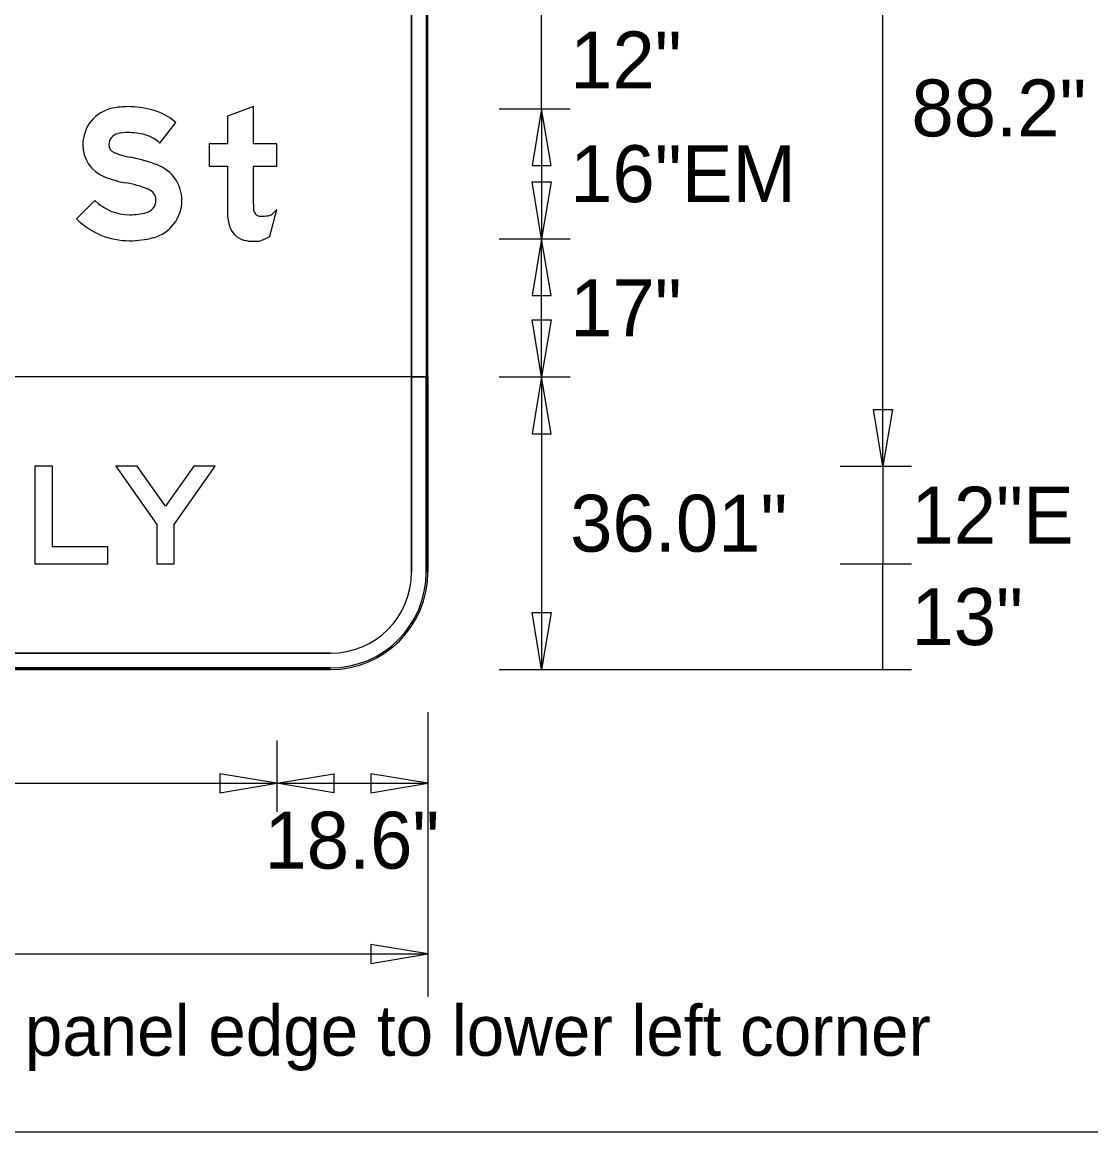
# Model space of a CAD drawing. Extents: x 2149934 to 2150188, y 145114 to 145238.
# Drawn here: x 2150101.62 to 2150112.58, y 145143.48 to 145154.85 of the extents above; entities that cross this region are included whole.
import ezdxf

# ---------------------------------------------------------------- set-up
doc = ezdxf.new("R2010")
doc.units = 0
for name, color, linetype in [('GSBWFILL', 7, 'Continuous'), ('GSCOLORFILL', 7, 'Continuous'), ('GSDIMS', 7, 'Continuous'), ('GSOUTLINE', 7, 'Continuous'), ('Level 1', 7, 'Continuous')]:
    doc.layers.add(name, color=color, linetype=linetype)

msp = doc.modelspace()

# ---------------------------------------------------------------- linework, layer by layer
at = {"layer": 'GSBWFILL'}
for p, q in [((2150105.612, 145163.216), (2150105.612, 145149.216)), ((2150105.779, 145149.216), (2150105.779, 145163.216)), ((2150104.159, 145152.659), (2150104.229, 145152.935)), ((2150105.779, 145151.217), (2150090.279, 145151.217)), ((2150105.612, 145151.05), (2150105.612, 145151.217)), ((2150105.612, 145151.217), (2150105.779, 145151.217)), ((2150105.779, 145151.217), (2150105.779, 145149.216)), ((2150105.779, 145149.216), (2150105.779, 145151.217)), ((2150105.612, 145149.216), (2150105.612, 145151.05)), ((2150091.279, 145148.383), (2150104.779, 145148.383)), ((2150104.779, 145148.383), (2150091.28, 145148.383)), ((2150104.779, 145148.216), (2150091.279, 145148.216)), ((2150091.279, 145148.216), (2150104.779, 145148.216)), ((2150091.28, 145148.216), (2150104.779, 145148.216))]:
    msp.add_line(p, q, dxfattribs=at)
for points in [[(2150103.989, 145152.987), (2150103.989, 145153.377), (2150104.229, 145153.377), (2150104.229, 145153.607), (2150103.989, 145153.607), (2150103.989, 145153.99), (2150103.723, 145153.889), (2150103.723, 145153.607), (2150103.536, 145153.607), (2150103.536, 145153.377), (2150103.723, 145153.377), (2150103.723, 145152.907)], [(2150103.03, 145153.615), (2150103.194, 145153.826)], [(2150102.364, 145153.026), (2150102.176, 145152.836)]]:
    msp.add_lwpolyline(points, dxfattribs=at)
for points in [[(2150102.498, 145149.3), (2150102.498, 145149.475), (2150101.928, 145149.475), (2150101.928, 145150.3), (2150101.748, 145150.3), (2150101.748, 145149.3)], [(2150103.178, 145149.705), (2150103.598, 145150.3), (2150103.378, 145150.3), (2150103.088, 145149.89), (2150102.799, 145150.3), (2150102.578, 145150.3), (2150102.998, 145149.705), (2150102.998, 145149.3), (2150103.178, 145149.3)]]:
    msp.add_lwpolyline(points, close=True, dxfattribs=at)
for radius in [1, 0.833, 1, 0.833, 1]:
    msp.add_arc((2150104.779, 145149.216), radius, 270, 0, dxfattribs=at)
for centre, major_axis, ratio, start_param, end_param in [((2150102.703, 145153.203), (0, 0.785), 0.999996, 0, 0.202758), ((2150102.703, 145153.025), (0, 0.963), 0.999996, 6.026234, 6.283185), ((2150102.622, 145153.598), (0, 0.382), 0.999996, 0.202758, 1.570796), ((2150102.792, 145153.365), (0, 0.611), 0.999996, 5.565152, 6.026234), ((2150102.622, 145153.598), (0, 0.115), 0.999996, 0.202758, 1.570796), ((2150102.703, 145153.203), (0, 0.519), 0.999996, 0, 0.202758), ((2150102.703, 145153.025), (0, 0.697), 0.999996, 6.026234, 6.283185), ((2150102.792, 145153.365), (0, 0.345), 0.999996, 5.523837, 6.026234), ((2150102.593, 145153.598), (0, 0.354), 0.999996, 1.570796, 2.761249), ((2150102.593, 145153.598), (0, 0.0872), 0.999996, 1.570796, 2.761249), ((2150102.884, 145154.325), (0, 0.87), 0.999996, 2.761249, 2.95744), ((2150102.427, 145151.874), (0, 1.623), 0.999996, 5.918637, 6.099033), ((2150102.868, 145153.027), (0, 0.388), 0.999996, 4.712389, 5.918637), ((2150102.884, 145154.325), (0, 1.137), 0.999996, 2.761249, 2.95744), ((2150102.427, 145151.874), (0, 1.357), 0.999996, 5.918637, 6.099033), ((2150102.868, 145153.027), (0, 0.122), 0.999996, 4.712389, 5.918637), ((2150102.719, 145153.384), (0, 0.504), 0.999996, 2.360607, 3.141593), ((2150102.86, 145153.027), (0, 0.129), 0.999996, 3.401517, 4.712389), ((2150102.86, 145153.027), (0, 0.396), 0.999996, 3.401517, 4.712389), ((2150105.659, 145152.987), (0, 1.669), 0.999994, 1.570796, 1.606005), ((2150102.719, 145153.558), (0, 0.678), 0.999996, 3.141593, 3.401517), ((2150104.24, 145152.907), (0, 0.517), 0.999994, 1.570796, 1.830698), ((2150104.066, 145152.941), (0, 0.0767), 0.999994, 1.74085, 2.407828), ((2150104.068, 145152.944), (0, 0.0803), 0.999994, 2.407828, 3.141593), ((2150104.068, 145153.285), (0, 0.421), 0.999994, 3.141593, 3.310762), ((2150104.123, 145152.968), (0, 0.1), 0.999994, 3.310762, 3.756278), ((2150104.054, 145153.066), (0, 0.219), 0.999994, 3.756278, 4.071638), ((2150102.719, 145153.384), (0, 0.771), 0.999996, 2.360607, 3.141593), ((2150103.95, 145152.829), (0, 0.217), 0.999994, 1.830698, 2.869526), ((2150102.719, 145153.558), (0, 0.945), 0.999996, 3.141593, 3.401517), ((2150103.989, 145152.972), (0, 0.365), 0.999994, 2.869526, 3.141593), ((2150103.981, 145152.921), (0, 0.317), 0.999994, 3.427755, 3.738844), ((2150103.989, 145153.133), (0, 0.526), 0.999994, 3.141593, 3.205734), ((2150104.009, 145152.824), (0, 0.217), 0.999994, 3.205734, 3.427755)]:
    msp.add_ellipse(centre, major_axis=major_axis, ratio=ratio, start_param=start_param, end_param=end_param, dxfattribs=at)
at = {"layer": 'GSCOLORFILL'}
for p, q in [((2150105.612, 145163.216), (2150105.612, 145149.216)), ((2150105.762, 145163.216), (2150105.762, 145149.216)), ((2150105.779, 145149.216), (2150105.779, 145163.216)), ((2150105.779, 145149.216), (2150105.779, 145163.216)), ((2150105.779, 145149.216), (2150105.779, 145163.216)), ((2150104.159, 145152.659), (2150104.229, 145152.935)), ((2150105.779, 145151.217), (2150090.279, 145151.217)), ((2150105.612, 145151.05), (2150105.612, 145151.217)), ((2150105.612, 145151.217), (2150105.779, 145151.217)), ((2150105.762, 145151.2), (2150105.762, 145151.217)), ((2150105.762, 145151.217), (2150105.779, 145151.217)), ((2150105.762, 145149.216), (2150105.762, 145151.2)), ((2150105.779, 145149.216), (2150105.779, 145151.217)), ((2150105.779, 145151.217), (2150105.779, 145149.216)), ((2150105.779, 145151.217), (2150105.779, 145149.216)), ((2150105.612, 145149.216), (2150105.612, 145151.05)), ((2150091.279, 145148.383), (2150104.779, 145148.383)), ((2150104.779, 145148.383), (2150091.28, 145148.383)), ((2150104.779, 145148.233), (2150091.279, 145148.233)), ((2150091.279, 145148.233), (2150104.779, 145148.233)), ((2150091.279, 145148.216), (2150104.779, 145148.216)), ((2150091.279, 145148.216), (2150104.779, 145148.216)), ((2150091.279, 145148.216), (2150104.779, 145148.216)), ((2150104.779, 145148.216), (2150091.279, 145148.216)), ((2150104.779, 145148.216), (2150091.279, 145148.216)), ((2150091.28, 145148.216), (2150104.779, 145148.216))]:
    msp.add_line(p, q, dxfattribs=at)
for points in [[(2150103.989, 145152.987), (2150103.989, 145153.377), (2150104.229, 145153.377), (2150104.229, 145153.607), (2150103.989, 145153.607), (2150103.989, 145153.99), (2150103.723, 145153.889), (2150103.723, 145153.607), (2150103.536, 145153.607), (2150103.536, 145153.377), (2150103.723, 145153.377), (2150103.723, 145152.907)], [(2150103.03, 145153.615), (2150103.194, 145153.826)], [(2150102.364, 145153.026), (2150102.176, 145152.836)]]:
    msp.add_lwpolyline(points, dxfattribs=at)
for points in [[(2150102.498, 145149.3), (2150102.498, 145149.475), (2150101.928, 145149.475), (2150101.928, 145150.3), (2150101.748, 145150.3), (2150101.748, 145149.3)], [(2150103.178, 145149.705), (2150103.598, 145150.3), (2150103.378, 145150.3), (2150103.088, 145149.89), (2150102.799, 145150.3), (2150102.578, 145150.3), (2150102.998, 145149.705), (2150102.998, 145149.3), (2150103.178, 145149.3)]]:
    msp.add_lwpolyline(points, close=True, dxfattribs=at)
for radius in [1, 1, 0.833, 1, 0.983, 1, 1, 0.833, 1, 0.983]:
    msp.add_arc((2150104.779, 145149.216), radius, 270, 0, dxfattribs=at)
for centre, major_axis, ratio, start_param, end_param in [((2150102.703, 145153.203), (0, 0.785), 0.999996, 0, 0.202758), ((2150102.703, 145153.025), (0, 0.963), 0.999996, 6.026234, 6.283185), ((2150102.622, 145153.598), (0, 0.382), 0.999996, 0.202758, 1.570796), ((2150102.792, 145153.365), (0, 0.611), 0.999996, 5.565152, 6.026234), ((2150102.622, 145153.598), (0, 0.115), 0.999996, 0.202758, 1.570796), ((2150102.703, 145153.203), (0, 0.519), 0.999996, 0, 0.202758), ((2150102.703, 145153.025), (0, 0.697), 0.999996, 6.026234, 6.283185), ((2150102.792, 145153.365), (0, 0.345), 0.999996, 5.523837, 6.026234), ((2150102.593, 145153.598), (0, 0.354), 0.999996, 1.570796, 2.761249), ((2150102.593, 145153.598), (0, 0.0872), 0.999996, 1.570796, 2.761249), ((2150102.884, 145154.325), (0, 0.87), 0.999996, 2.761249, 2.95744), ((2150102.427, 145151.874), (0, 1.623), 0.999996, 5.918637, 6.099033), ((2150102.868, 145153.027), (0, 0.388), 0.999996, 4.712389, 5.918637), ((2150102.884, 145154.325), (0, 1.137), 0.999996, 2.761249, 2.95744), ((2150102.427, 145151.874), (0, 1.357), 0.999996, 5.918637, 6.099033), ((2150102.868, 145153.027), (0, 0.122), 0.999996, 4.712389, 5.918637), ((2150102.719, 145153.384), (0, 0.504), 0.999996, 2.360607, 3.141593), ((2150102.86, 145153.027), (0, 0.129), 0.999996, 3.401517, 4.712389), ((2150102.86, 145153.027), (0, 0.396), 0.999996, 3.401517, 4.712389), ((2150105.659, 145152.987), (0, 1.669), 0.999994, 1.570796, 1.606005), ((2150102.719, 145153.558), (0, 0.678), 0.999996, 3.141593, 3.401517), ((2150104.24, 145152.907), (0, 0.517), 0.999994, 1.570796, 1.830698), ((2150104.066, 145152.941), (0, 0.0767), 0.999994, 1.74085, 2.407828), ((2150104.068, 145152.944), (0, 0.0803), 0.999994, 2.407828, 3.141593), ((2150104.068, 145153.285), (0, 0.421), 0.999994, 3.141593, 3.310762), ((2150104.123, 145152.968), (0, 0.1), 0.999994, 3.310762, 3.756278), ((2150104.054, 145153.066), (0, 0.219), 0.999994, 3.756278, 4.071638), ((2150102.719, 145153.384), (0, 0.771), 0.999996, 2.360607, 3.141593), ((2150103.95, 145152.829), (0, 0.217), 0.999994, 1.830698, 2.869526), ((2150102.719, 145153.558), (0, 0.945), 0.999996, 3.141593, 3.401517), ((2150103.989, 145152.972), (0, 0.365), 0.999994, 2.869526, 3.141593), ((2150103.981, 145152.921), (0, 0.317), 0.999994, 3.427755, 3.738844), ((2150103.989, 145153.133), (0, 0.526), 0.999994, 3.141593, 3.205734), ((2150104.009, 145152.824), (0, 0.217), 0.999994, 3.205734, 3.427755)]:
    msp.add_ellipse(centre, major_axis=major_axis, ratio=ratio, start_param=start_param, end_param=end_param, dxfattribs=at)
at = {"layer": 'GSDIMS'}
for p, q in [((2150110.445, 145150.3), (2150110.445, 145157.65)), ((2150106.945, 145153.967), (2150106.945, 145154.967)), ((2150106.508, 145153.967), (2150107.237, 145153.967)), ((2150106.508, 145153.967), (2150107.237, 145153.967)), ((2150106.945, 145153.967), (2150106.945, 145152.634)), ((2150106.508, 145152.634), (2150107.237, 145152.634)), ((2150106.508, 145152.634), (2150107.237, 145152.634)), ((2150106.945, 145151.217), (2150106.945, 145152.634)), ((2150106.508, 145151.217), (2150107.237, 145151.217)), ((2150106.508, 145151.217), (2150107.237, 145151.217)), ((2150106.945, 145151.217), (2150106.945, 145148.216)), ((2150110.008, 145150.3), (2150110.737, 145150.3)), ((2150110.008, 145150.3), (2150110.737, 145150.3)), ((2150110.445, 145150.3), (2150110.445, 145149.3)), ((2150110.008, 145149.3), (2150110.737, 145149.3)), ((2150110.008, 145149.3), (2150110.737, 145149.3)), ((2150110.445, 145148.216), (2150110.445, 145149.3)), ((2150106.508, 145148.216), (2150107.237, 145148.216)), ((2150106.508, 145148.216), (2150110.008, 145148.216)), ((2150110.008, 145148.216), (2150110.737, 145148.216)), ((2150105.779, 145147.779), (2150105.779, 145144.862)), ((2150104.229, 145147.487), (2150104.229, 145146.758)), ((2150104.229, 145147.487), (2150104.229, 145146.758)), ((2150105.779, 145147.487), (2150105.779, 145146.758)), ((2150091.828, 145147.05), (2150104.229, 145147.05)), ((2150104.229, 145147.05), (2150105.779, 145147.05)), ((2150105.779, 145145.737), (2150105.779, 145145.008)), ((2150090.279, 145145.3), (2150105.779, 145145.3))]:
    msp.add_line(p, q, dxfattribs=at)
for points in [[(2150106.945, 145153.967), (2150106.848, 145153.384), (2150107.043, 145153.384)], [(2150106.945, 145152.634), (2150106.848, 145153.217), (2150107.043, 145153.217)], [(2150106.945, 145152.634), (2150106.848, 145152.05), (2150107.043, 145152.05)], [(2150106.945, 145151.217), (2150106.848, 145151.801), (2150107.043, 145151.801)], [(2150106.945, 145151.217), (2150106.848, 145150.634), (2150107.043, 145150.634)], [(2150110.445, 145150.3), (2150110.348, 145150.883), (2150110.543, 145150.883)], [(2150106.945, 145148.216), (2150106.848, 145148.8), (2150107.043, 145148.8)], [(2150104.229, 145147.05), (2150103.646, 145147.147), (2150103.646, 145146.953)], [(2150104.229, 145147.05), (2150104.813, 145147.147), (2150104.813, 145146.953)], [(2150105.779, 145147.05), (2150105.195, 145147.147), (2150105.195, 145146.953)], [(2150105.779, 145145.3), (2150105.195, 145145.397), (2150105.195, 145145.203)]]:
    msp.add_lwpolyline(points, close=True, dxfattribs=at)
at = {"layer": 'GSOUTLINE'}
for p, q in [((2150105.612, 145149.216), (2150105.612, 145163.216)), ((2150105.779, 145149.216), (2150105.779, 145163.216)), ((2150104.159, 145152.659), (2150104.229, 145152.935)), ((2150105.779, 145151.217), (2150090.279, 145151.217)), ((2150105.612, 145151.05), (2150105.612, 145151.217)), ((2150105.612, 145151.217), (2150105.779, 145151.217)), ((2150105.779, 145151.217), (2150105.779, 145149.216)), ((2150105.779, 145149.216), (2150105.779, 145151.217)), ((2150105.612, 145149.216), (2150105.612, 145151.05)), ((2150091.279, 145148.383), (2150104.779, 145148.383)), ((2150091.279, 145148.383), (2150104.779, 145148.383)), ((2150091.279, 145148.216), (2150104.779, 145148.216)), ((2150104.779, 145148.216), (2150091.279, 145148.216)), ((2150091.279, 145148.216), (2150104.779, 145148.216))]:
    msp.add_line(p, q, dxfattribs=at)
for points in [[(2150103.989, 145152.987), (2150103.989, 145153.377), (2150104.229, 145153.377), (2150104.229, 145153.607), (2150103.989, 145153.607), (2150103.989, 145153.99), (2150103.723, 145153.889), (2150103.723, 145153.607), (2150103.536, 145153.607), (2150103.536, 145153.377), (2150103.723, 145153.377), (2150103.723, 145152.907)], [(2150103.03, 145153.615), (2150103.194, 145153.826)], [(2150102.364, 145153.026), (2150102.176, 145152.836)]]:
    msp.add_lwpolyline(points, dxfattribs=at)
for points in [[(2150102.498, 145149.3), (2150102.498, 145149.475), (2150101.928, 145149.475), (2150101.928, 145150.3), (2150101.748, 145150.3), (2150101.748, 145149.3)], [(2150103.178, 145149.705), (2150103.598, 145150.3), (2150103.378, 145150.3), (2150103.088, 145149.89), (2150102.799, 145150.3), (2150102.578, 145150.3), (2150102.998, 145149.705), (2150102.998, 145149.3), (2150103.178, 145149.3)]]:
    msp.add_lwpolyline(points, close=True, dxfattribs=at)
for radius in [1, 0.833, 1, 0.833, 1]:
    msp.add_arc((2150104.779, 145149.216), radius, 270, 0, dxfattribs=at)
for centre, major_axis, ratio, start_param, end_param in [((2150102.703, 145153.203), (0, 0.785), 0.999996, 0, 0.202758), ((2150102.703, 145153.025), (0, 0.963), 0.999996, 6.026234, 6.283185), ((2150102.622, 145153.598), (0, 0.382), 0.999996, 0.202758, 1.570796), ((2150102.792, 145153.365), (0, 0.611), 0.999996, 5.565152, 6.026234), ((2150102.622, 145153.598), (0, 0.115), 0.999996, 0.202758, 1.570796), ((2150102.703, 145153.203), (0, 0.519), 0.999996, 0, 0.202758), ((2150102.703, 145153.025), (0, 0.697), 0.999996, 6.026234, 6.283185), ((2150102.792, 145153.365), (0, 0.345), 0.999996, 5.523837, 6.026234), ((2150102.593, 145153.598), (0, 0.354), 0.999996, 1.570796, 2.761249), ((2150102.593, 145153.598), (0, 0.0872), 0.999996, 1.570796, 2.761249), ((2150102.884, 145154.325), (0, 0.87), 0.999996, 2.761249, 2.95744), ((2150102.427, 145151.874), (0, 1.623), 0.999996, 5.918637, 6.099033), ((2150102.868, 145153.027), (0, 0.388), 0.999996, 4.712389, 5.918637), ((2150102.884, 145154.325), (0, 1.137), 0.999996, 2.761249, 2.95744), ((2150102.427, 145151.874), (0, 1.357), 0.999996, 5.918637, 6.099033), ((2150102.868, 145153.027), (0, 0.122), 0.999996, 4.712389, 5.918637), ((2150102.719, 145153.384), (0, 0.504), 0.999996, 2.360607, 3.141593), ((2150102.86, 145153.027), (0, 0.129), 0.999996, 3.401517, 4.712389), ((2150102.86, 145153.027), (0, 0.396), 0.999996, 3.401517, 4.712389), ((2150105.659, 145152.987), (0, 1.669), 0.999994, 1.570796, 1.606005), ((2150102.719, 145153.558), (0, 0.678), 0.999996, 3.141593, 3.401517), ((2150104.24, 145152.907), (0, 0.517), 0.999994, 1.570796, 1.830698), ((2150104.066, 145152.941), (0, 0.0767), 0.999994, 1.74085, 2.407828), ((2150104.068, 145152.944), (0, 0.0803), 0.999994, 2.407828, 3.141593), ((2150104.068, 145153.285), (0, 0.421), 0.999994, 3.141593, 3.310762), ((2150104.123, 145152.968), (0, 0.1), 0.999994, 3.310762, 3.756278), ((2150104.054, 145153.066), (0, 0.219), 0.999994, 3.756278, 4.071638), ((2150102.719, 145153.384), (0, 0.771), 0.999996, 2.360607, 3.141593), ((2150103.95, 145152.829), (0, 0.217), 0.999994, 1.830698, 2.869526), ((2150102.719, 145153.558), (0, 0.945), 0.999996, 3.141593, 3.401517), ((2150103.989, 145152.972), (0, 0.365), 0.999994, 2.869526, 3.141593), ((2150103.981, 145152.921), (0, 0.317), 0.999994, 3.427755, 3.738844), ((2150103.989, 145153.133), (0, 0.526), 0.999994, 3.141593, 3.205734), ((2150104.009, 145152.824), (0, 0.217), 0.999994, 3.205734, 3.427755)]:
    msp.add_ellipse(centre, major_axis=major_axis, ratio=ratio, start_param=start_param, end_param=end_param, dxfattribs=at)
at = {"layer": 'Level 1'}
msp.add_line((2150076.316, 145143.476), (2150121.342, 145143.476), dxfattribs=at)

# ---------------------------------------------------------------- texts
at = {"layer": 'GSDIMS'}
for s, p in [('12"', (2150107.237, 145154.175)), ('88.2"', (2150110.737, 145153.683)), ('16"EM', (2150107.237, 145153.009)), ('17"', (2150107.237, 145151.634)), ('36.01"', (2150107.237, 145149.425)), ('12"E', (2150110.737, 145149.508)), ('13"', (2150110.737, 145148.467)), ('18.6"', (2150104.102, 145146.175))]:
    msp.add_text(s, height=0.5833, dxfattribs=at).set_placement(p)
at = {"layer": 'Level 1'}
msp.add_text('Letter locations are panel edge to lower left corner', height=0.51652, dxfattribs=at).set_placement((2150095.579, 145144.256))

doc.saveas('drawing.dxf')
